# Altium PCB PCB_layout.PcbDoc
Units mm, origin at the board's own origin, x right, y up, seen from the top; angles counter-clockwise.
Board outline 62 x 48 mm, 2 copper layers (Top Layer, Bottom Layer); 48 components, 23 nets, 137 pads, 16 vias.
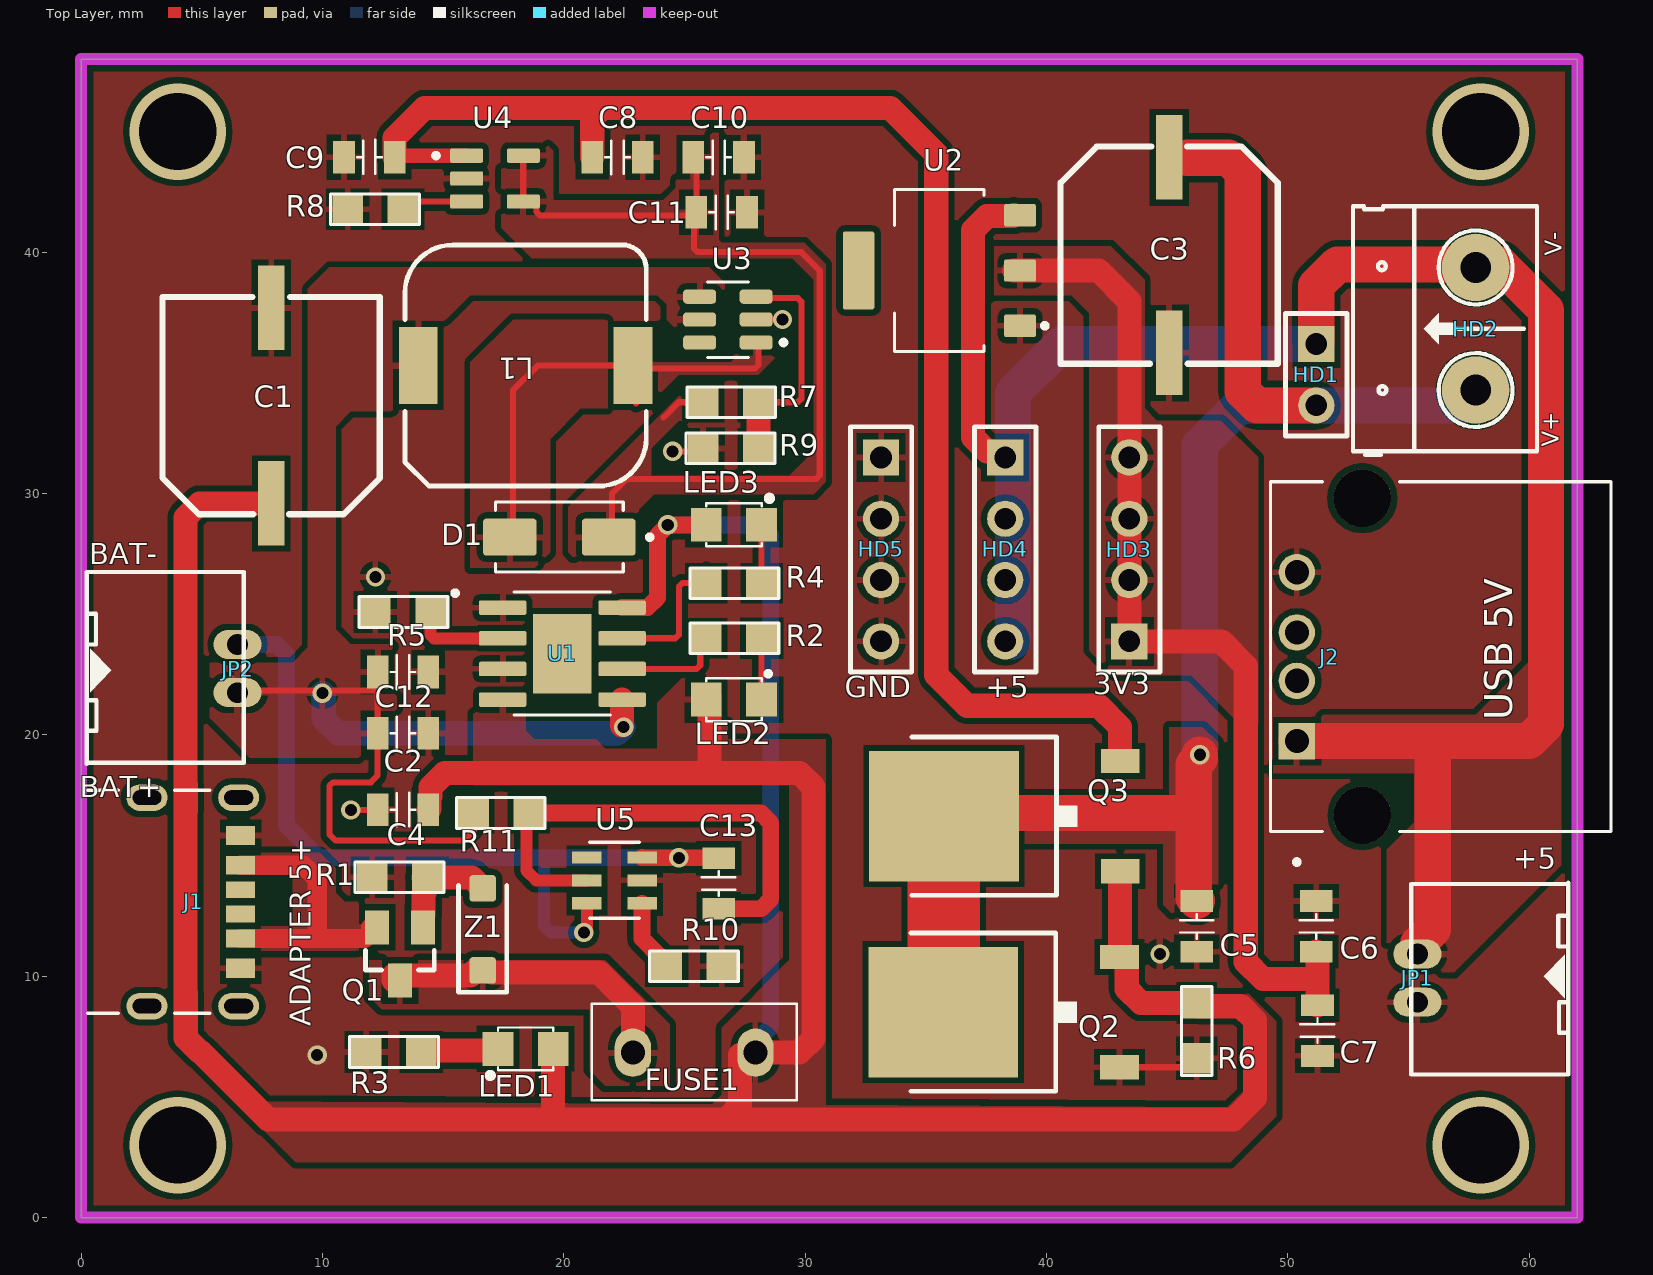
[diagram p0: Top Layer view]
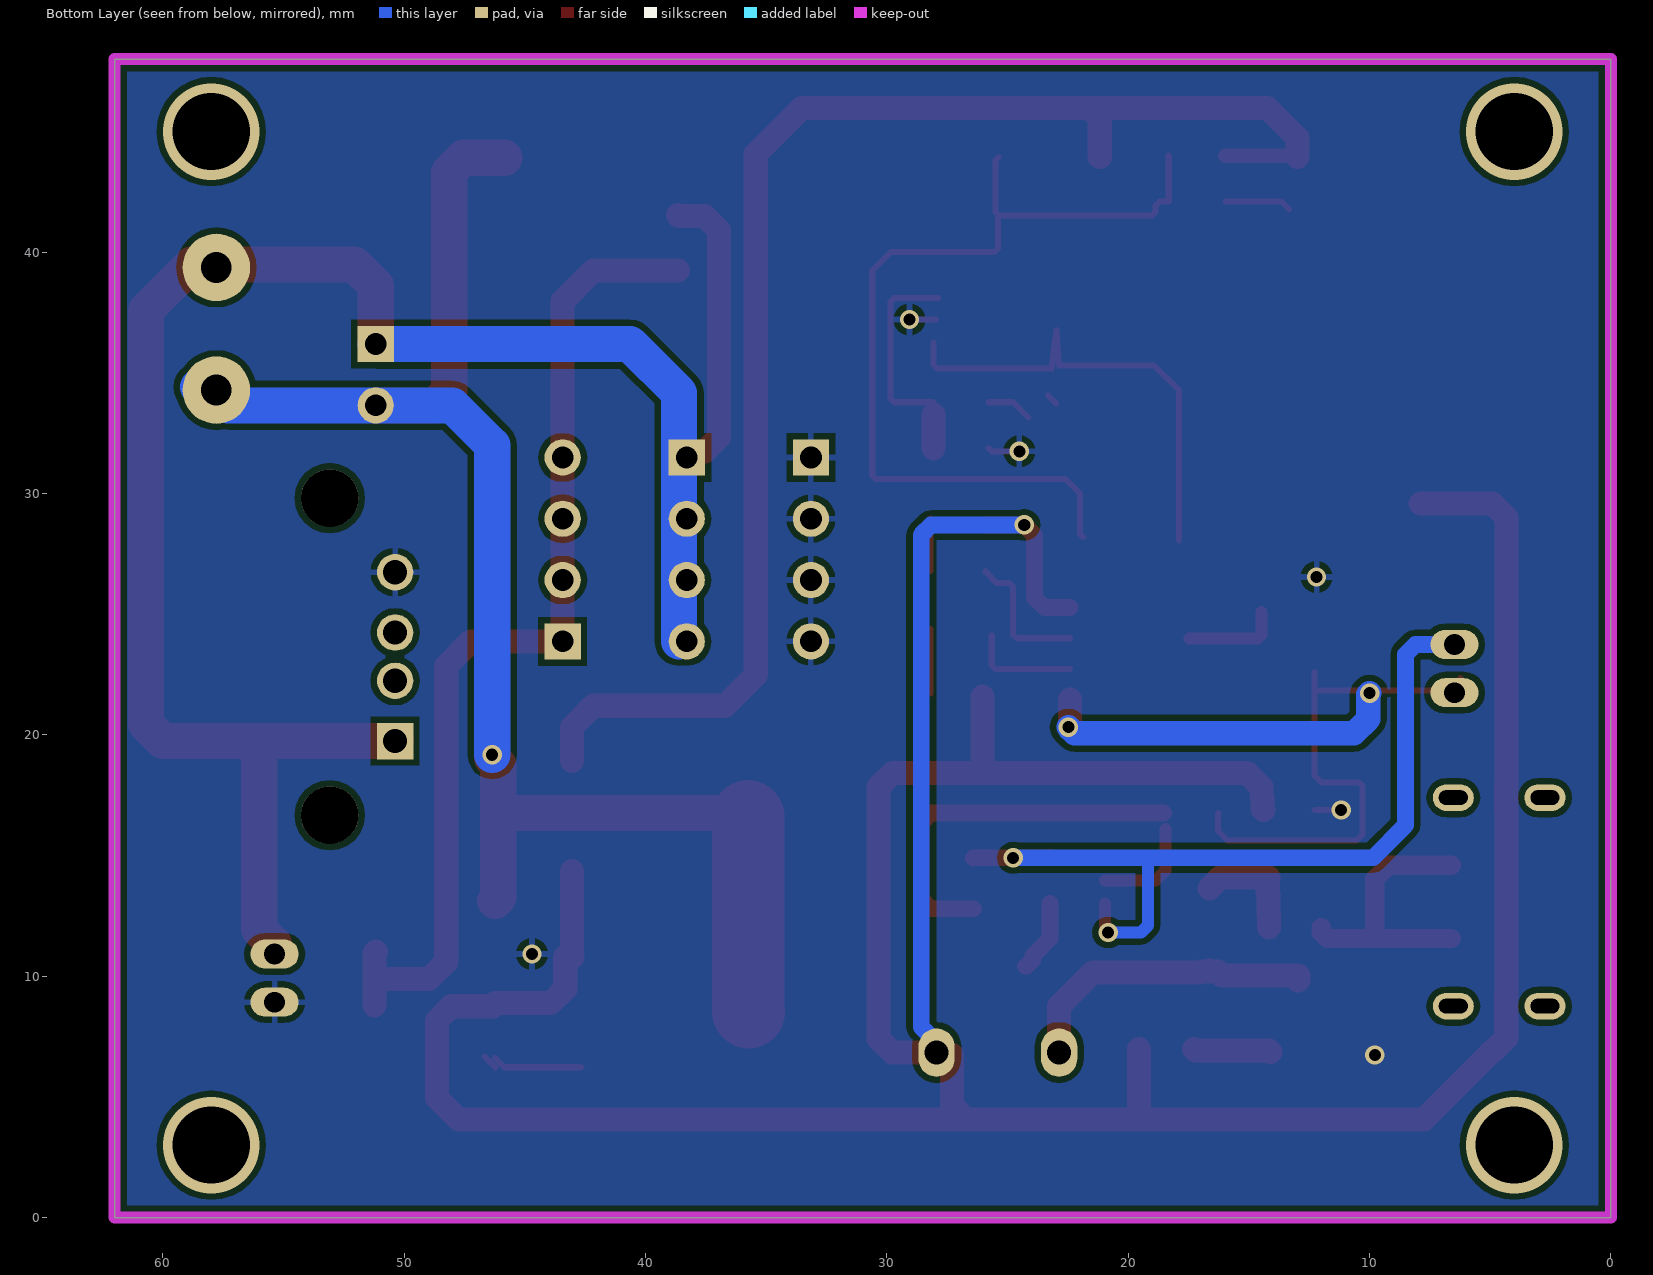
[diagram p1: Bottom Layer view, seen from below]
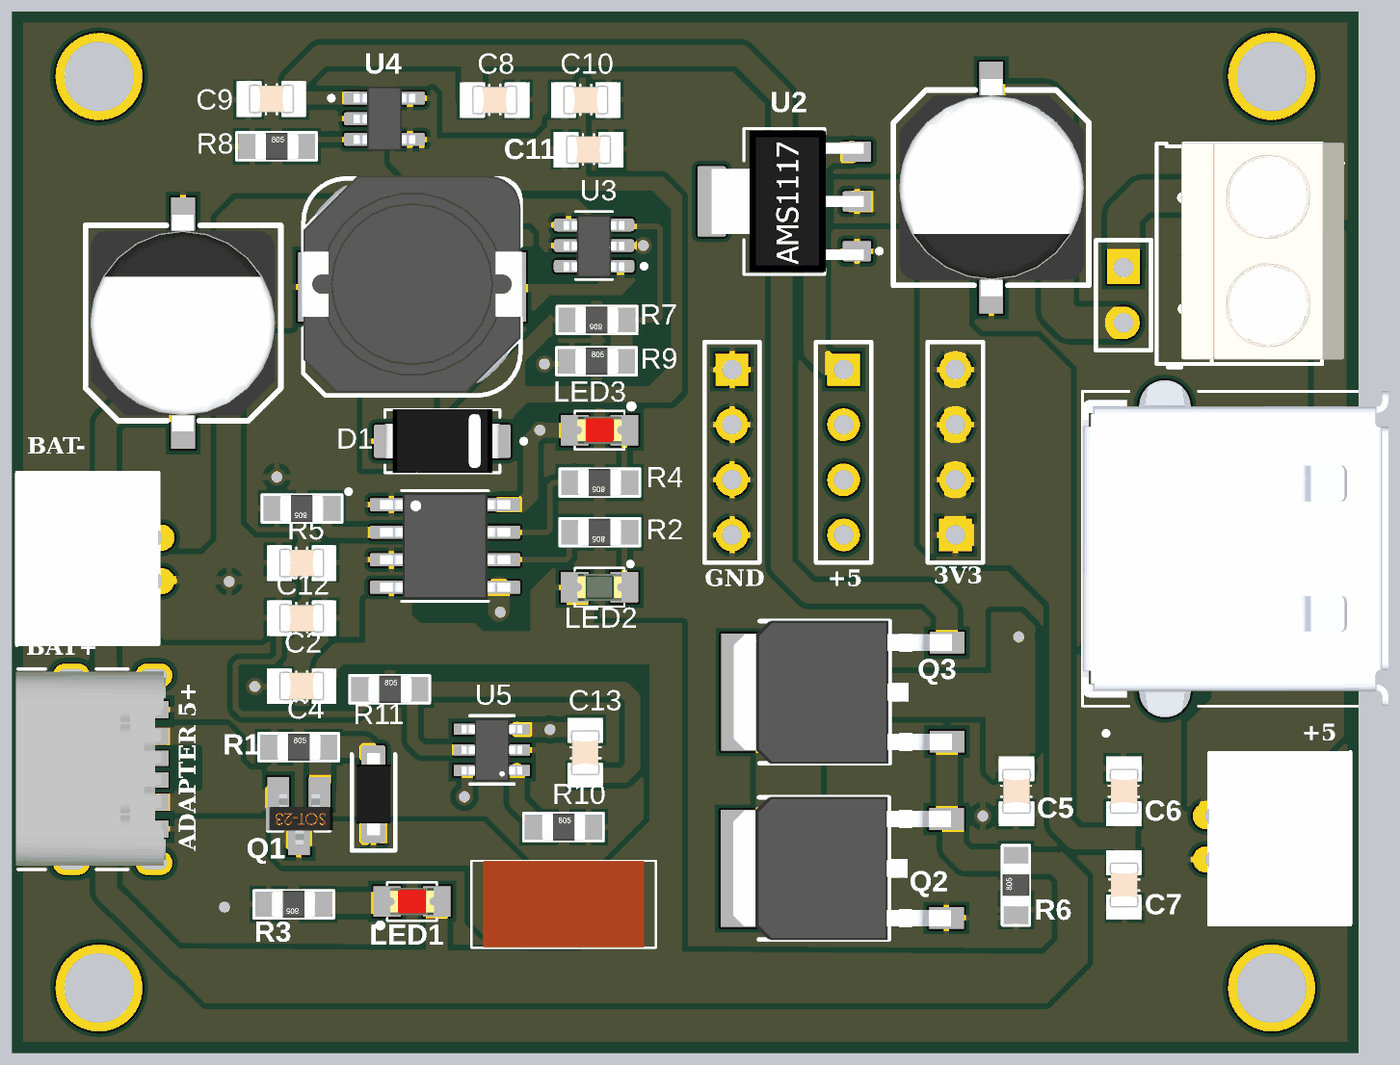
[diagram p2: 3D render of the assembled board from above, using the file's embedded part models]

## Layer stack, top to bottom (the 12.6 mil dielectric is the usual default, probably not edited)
Top Solder: solder mask 0.0102, Solder Resist, Dk 3.5
Top Layer: signal copper 0.0356
Dielectric 1: dielectric 0.32, FR-4, Dk 4.8
Bottom Layer: signal copper 0.0356
Bottom Solder: solder mask 0.0102, Solder Resist, Dk 3.5

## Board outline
0,0 0,48 62,48 62,0

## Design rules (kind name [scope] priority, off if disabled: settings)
Clearance [All] p1: gap=0.254 ignorepadtopadclearanceinfootprint=FALSE except(0: Arc-Hole Track-Hole SMDPad-Hole THPad-Hole Via-Hole Fill-Hole Poly-Hole Region-Hole Text-Hole)
HoleSize [All] p1: absolutevalues=TRUE maxlimit=1000 minlimit=0.5 maxpercent=80.000 minpercent=20.000
HoleToHoleClearance [All] p1 off: gap=0.254 allowstackedmicrovias=TRUE
MinimumSolderMaskSliver [All] p1 off: minsoldermaskwidth=0.254
PolygonConnect [All] p1: connectstyle=Relief reliefconductorwidth=0.254 reliefentries=4 polygonreliefangle="90 Angle" airgapwidth=0.254
RoutingVias [All] p1: holewidth=0.711 width=1.27 viastyle="Through Hole" minholewidth=0.5 minwidth=0.8 maxholewidth=1000 maxwidth=1000
SilkToSilkClearance [All] p1 off: silktosilkclearance=0.254
SilkToSolderMaskClearance [IsPad] p1 off: minsilkscreentomaskgap=0.254 clearancetoexposedcopper=TRUE
SolderMaskExpansion [All] p1: expansion=0.102 istentingtop=FALSE
Width [All] p1: maxlimit=1000 minlimit=0.254 preferedwidth=0.5
25 further rules are at their usual default settings.

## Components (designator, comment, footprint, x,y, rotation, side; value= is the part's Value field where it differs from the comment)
C1 "680uF" "Capacitor 680uF" 7.874,33.641 r90 top
C2 "22uF" "C 0805" 13.335,20.066 r180 top value=103
C3 "680uF" "Capacitor 680uF" 45.085,39.878 r270 top
C4 "22uF" "C 0805" 13.335,16.891 r0 top value=103
C5 "22uF" "C 0805" 46.228,12.065 r270 top value=103
C6 "100nF" "C 0805" 51.231,7.747 r90 top value=103
C7 "10uF" "C 0805" 51.181,12.065 r270 top value=103
C8 "100nF" "C 0805" 22.225,43.942 r180 top value=103
C9 "10uF" "C 0805" 11.938,43.942 r0 top value=103
C10 "1uF" "C 0805" 26.416,43.942 r180 top value=103
C11 "47uF" "C 0805" 26.543,41.656 r180 top value=103
C12 "22uF" "C 0805" 13.335,22.606 r180 top value=103
C13 "100nF" "C 0805" 26.416,13.843 r90 top value=103
D1 "Diode" DIODE_1N4007 19.812,28.194 r180 top value=1N5007
FUSE1 "FUSE_392" FUSE_392 25.4,6.858 r0 top
HD1 "Header_2" HDR1X2 51.181,36.195 r270 top value="Connector 2"
HD2 "Header 2" HED2 57.785,34.29 r90 top
HD3 "JP4" HDR1X4 43.434,23.876 r90 top value="Connector 4"
HD4 "JP4" HDR1X4 38.291,31.496 r270 top value="Connector 4"
HD5 "JP4" HDR1X4 33.147,31.496 r270 top value="Connector 4"
J1 "USB-C_6pin" MOLEX_2171750001 0.127,13.081 r270 top
J2 "USB-A1HSW6" OST_USB-A1HSW6 53.086,23.241 r90 top
JP1 "Domino_cong2_PH2.0" CON2_PH2.0_Cong 55.372,8.922 r90 top value="Connector 2"
JP2 "Domino_cong2_PH2.0" CON2_PH2.0_Cong 6.477,23.749 r270 top value="Connector 2"
L1 "22uH" CDRH104R 18.415,35.306 r90 top
LED1 "LED SMD" SM-LED-0805-Red 19.558,6.985 r180 top
LED2 "LED SMD" SM-LED-0805-Green 25.908,21.463 r0 top
LED3 "LED SMD" SM-LED-0805-Red 25.908,28.702 r0 top
Q1 "SI2301DS" MOSFET_P 13.208,10.922 r180 top
Q2 "AOD4185" TO252 38.227,8.509 r90 top
Q3 "AOD4185" TO252 38.253,16.631 r90 top
R1 "10K" SM-RES-0805 12.065,14.097 r0 top value=1K
R2 "1K" SM-RES-0805 28.194,24.003 r180 top
R3 "1K" SM-RES-0805 14.097,6.858 r180 top
R4 "1K" SM-RES-0805 28.194,26.289 r180 top
R5 "1.2K" SM-RES-0805 14.478,25.093 r180 top value=1K
R6 "10K" SM-RES-0805 46.228,6.604 r90 top value=1K
R7 "150K" SM-RES-0805 28.067,33.782 r180 top value=1K
R8 "12K" SM-RES-0805 11.049,41.783 r0 top value=1K
R9 "20K" SM-RES-0805 25.781,31.877 r0 top value=1K
R10 "100R" SM-RES-0805 24.257,10.414 r0 top value=1K
R11 "100R" SM-RES-0805 16.256,16.764 r0 top value=1K
U1 "TP4056" SOP127P600X175-9N 19.939,23.368 r0 top
U2 "AMS1117-3.3" SOT229P700X180-4N 35.56,39.243 r90 top
U3 "MT3608" SOT95P280X145-6N 26.797,37.211 r180 top
U4 "SY6280AAC" SOT95P285X130-5N 17.145,43.053 r0 top
U5 "DW06" TSOT-23_S6 22.098,13.97 r180 top
Z1 "Zener-Diode" SOD-123F 16.637,11.938 r90 top value=Z-Diode (schematic designator *1)

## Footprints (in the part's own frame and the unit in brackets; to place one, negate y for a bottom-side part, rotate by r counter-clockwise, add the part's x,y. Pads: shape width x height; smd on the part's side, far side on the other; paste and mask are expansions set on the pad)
"C 0805" [mm]
  rect 0.9x1.35 smd: 1(-1.05,0) 2(1.05,0)
  silkscreen extent -0.51,-0.69 0.51,0.71, body extent -1.6,-0.8 1.6,0.85, height 0.82
"Capacitor 680uF" [mm]
  rect 3.5x1.1 smd: 1(-4.05,0) 2(4.05,0)
  silkscreen extent -4.5,-4.5 4.5,4.5, body extent -5,-4.23 5,4.27, height 10.5
CDRH104R [mm]
  rect 3.2x1.6 smd: 1(0,4.45) 2(0,-4.45)
  silkscreen extent -5,-5 5,5, body extent -4.87,-5.1 5.13,5.1, height 4
CON2_PH2.0_Cong [mm] "CON2"
  oval 1.2x2 hole 0.864: 1(0,0) 2(2,0)
  silkscreen extent -3,-6.25 4.95,0.25, body extent -3.01,-6.35 4.94,0.25, height 5.2
DIODE_1N4007 [mm]
  rrect15% 2.21x1.53 smd: 1(2.05,0) 2(-2.05,0)
  silkscreen extent -3.85,-1.45 2.65,1.45, body extent -2.64,-1.47 2.64,1.45, height 2.41
FUSE_392 [mm]
  oval 1.5x2 hole 1: 1(-2.54,-0.025) 2(2.54,-0.025)
  silkscreen extent -4.25,-2 4.25,2, body extent -3.7,-2 3.7,2, height 8.3
HDR1X2 [mm] "Connector; Header; 2 Position"
  rect 1.5x1.5 hole 0.9: 1(0,0)
  round 1.5 hole 0.9: 2(2.54,0)
  silkscreen extent -1.27,-1.27 3.81,1.27, body extent -1.27,-1.27 3.81,1.27, height 7
HDR1X4 [mm] "Connector; Header; 4 Position"
  rect 1.5x1.5 hole 0.9: 1(0,0)
  round 1.5 hole 0.9: 2(2.54,0) 3(5.08,0) 4(7.62,0)
  silkscreen extent -1.27,-1.27 8.89,1.27, body extent -1.27,-1.27 8.89,1.27, height 7
HED2 [mil] "Header 2, 2 pin, hight 300mil, Pin to Pin 200, Colour Green"
  round 110 hole 50: 1(0,0) 2(200,0)
  silkscreen extent -106,-100 300,200, body extent -92,-140 302,155, height 394
MOLEX_2171750001 [mm]
  rect 0.7x1.2 smd mask+0.064: A5(-0.5,6.48) B5(0.5,6.48)
  rect 0.76x1.2 smd mask+0.064: A9(1.52,6.48) B9(-1.52,6.48)
  rect 0.8x1.2 smd mask+0.064: A12(2.75,6.48) B12(-2.75,6.48)
  oval 1.1x1.7 hole 0.6 slot 1.2 at 90 deg mask+0.064: SH1(-4.32,2.6) SH2(4.32,2.6) SH3(-4.32,6.4) SH4(4.32,6.4)
  silkscreen extent -4.62,0.15 4.62,5.2, body extent -4.5,0.05 4.44,6.95, height 3.28
MOSFET_P [mm]
  rect 1x1.4 smd: 1(-0.95,-1.1) 2(0.95,-1.1) 3(0,1.1)
  silkscreen extent -1.42,-0.15 1.42,0.66, body extent -1.57,-1.02 1.52,1.33, height 0.93
OST_USB-A1HSW6 [mm]
  rect 1.508x1.508 / inner round 1.508 / far side rect 1.508x1.508 hole 1: 1(-3.5,2.71)
  round 1.508 hole 1: 2(-1,2.71) 3(1,2.71) 4(3.5,2.71)
  round 2.38 hole 2.38 unplated: ""(-6.57,0) ""(6.57,0)
  silkscreen extent -8.61,-10.3 7.25,3.8, body extent -7.9,-10.3 7.9,3.8, height 7.6
SM-LED-0805-Green [mil]
  rect 50x55 smd: 1(0,0) 2(90,0)
  silkscreen extent 0,-35 104,45, body extent 5,-25 85,25, height 43
SM-LED-0805-Red [mil]
  rect 50x55 smd: 1(0,0) 2(90,0)
  silkscreen extent 0,-35 107,47, body extent 5,-25 85,25, height 43
SM-RES-0805 [mil]
  rect 50x47 smd: 1(0,0) 2(90,0)
  silkscreen extent -28,-25 117,25, body extent 6,-25 84,25, height 31
SOD-123F [mm] "SMD"
  rrect25% 1.1x1.1 smd: 1(-1.7,0) 2(1.7,0)
  silkscreen extent -2.6,-1 1.83,1, body extent -1.9,-0.8 1.9,0.8, height 1
SOP127P600X175-9N [mm]
  rrect25% 1.97x0.6 smd: 1(-2.475,1.905) 2(-2.475,0.635) 3(-2.475,-0.635) 4(-2.475,-1.905) 5(2.475,-1.905) 6(2.475,-0.635) 7(2.475,0.635) 8(2.475,1.905)
  rect 2.413x3.302 smd paste-3: 9(0,0)
  silkscreen extent -4.54,-2.55 2,2.6, body extent -3,-2.45 3,2.45, height 1.75
SOT95P280X145-6N [mm]
  rrect50% 1.37x0.59 smd: 1(-1.17,0.95) 2(-1.17,0) 3(-1.17,-0.95) 4(1.17,-0.95) 5(1.17,0) 6(1.17,0.95)
  silkscreen extent -2.4,-1.57 0.85,1.57, body extent -1.4,-1.42 1.4,1.48, height 1.45
SOT95P285X130-5N [mm]
  rrect25% 1.37x0.59 smd: 1(-1.175,0.95) 2(-1.175,0) 3(-1.175,-0.95) 4(1.175,-0.95) 5(1.175,0.95)
  silkscreen extent -2.54,0.85 -2.34,1.05, body extent -1.43,-1.48 1.43,1.48, height 1.4
SOT229P700X180-4N [mm]
  rrect15% 0.93x1.31 smd: 1(-2.29,-3.345) 2(0,-3.345) 3(2.29,-3.345)
  rrect15% 3.24x1.31 smd: 4(0,3.345)
  silkscreen extent -3.36,-4.47 3.36,1.86, body extent -3.25,-3.65 3.25,3.35, height 1.5
TO252 [mm]
  rect 1x1.6 smd: 1(-2.28,-4.8) 2(2.28,-4.8)
  rect 5.4x6.2 smd: 3(0,2.5)
  silkscreen extent -3.28,-3.02 3.28,3.84, body extent -3.3,-5.02 3.3,5.02, height 2.4
TSOT-23_S6 [mil]
  rect 48x20 smd paste+0 mask+4.02: 1(-45,37.4) 2(-45,0) 3(-45,-37.4) 4(45,-37.4) 5(45,0) 6(45,37.4)
  silkscreen extent -40,-62 40,62, body extent -55,-57 55,57, height 39

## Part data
C1 C3: library part Cap_680uF_SMD, "Cap SMD"
C2 C4 C5 C6 C7 C8 C9 C10 C11 C12 C13: library part "CAP SMD", "Cap SMD"
D1: library part Diode_1n4007, "Default Diode"
FUSE1: "Fuse Block 20A 500V 1 Circuit Blade Through Hole", Package=None
HD1: "Connector 2.54  2 PIN"
HD2: library part Header_green_2pin, "Header 2 (Green)"
HD3 HD4 HD5: library part Header_4, "Connector 2.54  4 PIN"
J1: "USB-C (USB TYPE-C) USB 2.0 Receptacle Connector 24 (6+18 Dummy) Position Surface Mount, Right Angle; Through Hole", Package=None
J2: Package=None
JP1 JP2: "Connector 2"
L1: library part INDUCTORS_CDRH104R, "POWER INDUCTORS (SMD Type)", Package=None
LED1 LED2 LED3: library part LED-SMD-0805
Q1: "N-Channel 50V 500mA _Ta_ 600mW _Ta_ Surface Mount SOT-23", Package="SC-59 NXP Semiconductors"
Q2 Q3: "P-Channel 40V 40A (Tc) 2.5W (Ta), 62.5W (Tc) Surface Mount TO-252, (D-Pak)", Package="TO-252 Alpha &amp; Omega Semiconductor"
R1 R2 R3 R4 R5 R6 R7 R8 R9 R10 R11: library part Resistor, "Resistor SMD"
U1: "Complete single cell Li-Ion battery with a constant current / constant voltage linear charger", Package=Package
U2: "Sot223/Pkg 1-Amp 3.3-Volt Low Drop Out Voltage Regulatator", Package=None
U3: "High Efficiency 1.2MHz2A Step Up Converter", Package=Package
U4: "USB Power Distribution SW Single 5.5V 1A 5-Pin SOT-23", Package="SOT-23-5 Silergy"
U5: "LT1784 - 2.5MHz, Over-The-Top Low Power, Rail-to-Rail Input and Output Op Amp in SOT-23", Package="SOT-23-6 Linear Technology"
Z1: "Zener Diode, TVS-unidirectional Diode", Supplier Part Number 1=637-BZT52B2V7

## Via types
v1: diameter 0.8, hole 0.5, Top Layer to Bottom Layer, tented both sides, 12 vias
v2: diameter 4, hole 3.2, Top Layer to Bottom Layer, 4 vias

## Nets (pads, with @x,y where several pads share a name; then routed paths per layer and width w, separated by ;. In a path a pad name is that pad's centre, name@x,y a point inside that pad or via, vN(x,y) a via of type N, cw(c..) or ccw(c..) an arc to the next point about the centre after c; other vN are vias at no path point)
3V3: C6.2 C7.2 HD3.1 HD3.2 HD3.3 HD3.4 U2.2 | length 42.4
  Top Layer w1: U2.2@38.651,39.243 42.164,39.243 43.434,37.973 HD3.4 HD3.3 HD3.2 HD3.1 47.244,23.876 48.26,22.86 48.26,10.595 48.974,9.881 51.231,9.881 ; C7.2 51.231,10.965 51.231,9.881 ; C6.2 51.231,9.881
+5V: C3.1 C5.1 HD1.2 HD2.1 Q2.3 Q3.3 | length 65.7
  Top Layer w1.5: Q3.3 35.886,16.764 36.763,16.764 46.101,16.764 ; 45.847,43.914 47.547,43.914 48.133,43.328 48.133,34.241 48.719,33.655 HD1.2 ; C5.1 46.101,13.242 46.101,16.764 ; v1(46.355,19.177) 46.355,19.029 46.101,18.775 46.101,16.764
  Top Layer w3: Q2.3 35.74,8.522 35.74,16.618 Q3.3
  Bottom Layer w1.5: v1(46.355,19.177) 46.355,32.004 48.006,33.655 51.943,33.655 57.3,33.655 58.062,34.417 HD2.1@58.547,34.417
ADAPTER: C1.1 C4.2 FUSE1.2 LED1.1 LED2.1 LED3.1 Q2.2 Q3.1 R6.2 U1.4 U1.8 | length 158.4
  Top Layer w0.7: U1.8 23.466,25.273 23.876,25.683 23.876,28.271 v1(24.307,28.702) LED3.1
  Top Layer w1: C1.1 4.904,29.591 4.318,29.005 4.318,17.954 4.331,17.941 4.331,16.861 4.318,16.848 4.318,9.314 4.331,9.301 4.331,7.444 4.917,6.858 4.953,6.858 7.747,4.064 19.558,4.064 ; C4.2 14.435,16.941 14.435,17.43 14.478,17.473 14.478,17.829 15.064,18.415 17.464,18.415 26.035,18.415 ; LED1.1 19.558,4.064 ; LED2.1@26.035,21.59 26.035,18.415 ; FUSE1.2@27.94,6.731 27.305,6.731 27.305,4.65 26.719,4.064 ; FUSE1.2 29.767,6.833 30.353,7.418 30.353,17.829 29.767,18.415 26.035,18.415 ; Q2.2 Q2.2@43.053,10.789 ; Q3.1 Q2.2@43.053,10.789 ; 19.558,4.064 26.719,4.064 ; 26.719,4.064 47.752,4.064 48.641,4.953 48.641,8.169 48.055,8.755 46.325,8.755 46.228,8.852 R6.2 43.913,8.89 43.327,9.476 43.327,10.789 Q2.2@43.053,10.789
  Bottom Layer w0.7: v1(24.307,28.702) 28.165,28.702 28.575,28.292 28.575,7.893 27.94,7.258 FUSE1.2
BAT+: C2.2 C12.2 JP2.2 L1.1 R11.1 U1.5 U3.4 U3.5 | length 37
  Top Layer w0.254: 6.223,22.352 6.731,21.844 v1@9.894,21.844 ; v1(9.994,21.729) 9.994,21.744 v1@9.894,21.844 ; C12.2 12.285,21.717 ; R11.1 16.278,16.742 16.278,16.024 15.875,15.621 10.541,15.621 10.287,15.875 10.287,17.885 10.436,18.034 11.997,18.034 12.285,18.322 C2.2 12.285,21.717 ; v1@22.414,20.385 v1(22.479,20.32) ; v1@9.894,21.844 12.158,21.844 12.285,21.717
  Top Layer w1: v1@22.414,20.385 U1.5
  Bottom Layer w1: v1(9.994,21.729) 10.052,21.671 10.052,20.652 10.638,20.066 22.225,20.066 v1(22.479,20.32)
BAT-: C13.2 JP2.1 U5.3 U5.6 | length 35.1
  Top Layer w0.5: v1(20.828,11.811) 20.955,11.938 U5.6
  Top Layer w0.7: U5.3 23.255,14.907 v1(24.765,14.907) 26.402,14.907 C13.2
  Bottom Layer w0.5: 19.177,14.907 19.177,12.104 19.47,11.811 v1(20.828,11.811)
  Bottom Layer w0.7: JP2.1 8.099,23.749 8.509,23.339 8.509,16.256 9.858,14.907 19.177,14.907 v1(24.765,14.907)
BOOT_5V: C8.2 C9.2 Q3.2 U4.1 | length 60.8
  Top Layer w0.6: C9.2@13.43,44.003 U4.1
  Top Layer w1: C9.2 12.988,44.738 14.224,45.974 21.175,45.974 21.463,45.974 21.526,45.91 ; C8.2 21.175,45.119 21.175,45.559 21.59,45.974 33.528,45.974 35.433,44.069 35.433,22.479 36.703,21.209 42.164,21.209 43.048,20.325 43.048,18.911 Q3.2
GND: C1.2 C2.1 C3.2 C4.1 C5.2 C6.1 C7.1 C8.1 C9.1 C10.1 C11.1 C12.1 HD5.1 HD5.2 HD5.3 HD5.4 J1.A12 J1.B12 J2.4 JP1.1 Q2.1 R1.1 R3.2 R5.2 R6.1 R8.1 R9.1 R10.2 U1.1 U1.3 U2.1 U3.2 U4.2 U5.2 | length 7.9
  Top Layer w0.254: v1(11.176,16.891) C4.1 ; v1(24.511,31.75) 25.654,31.75 R9.1 ; U3.2 v1(29.064,37.211) ; Q2.1@42.663,6.229 45.853,6.229 R6.1 ; R6.1@46.228,6.229 R6.1@46.67,6.671
  other v1: 9.779,6.731 44.704,10.922 12.192,26.543
INPUT: J1.A9 J1.B9 Q1.2 | length 11.6
  Top Layer w0.8: J1.A9 9.779,11.561 ; J1.B9 9.193,14.601 9.779,14.015 9.779,11.561 ; Q1.2@12.004,12.022 12.004,11.822 11.743,11.561 9.779,11.561
Net*1_1: FUSE1.1 Q1.3 Z1.1 | length 12.7
  Top Layer w1: Q1.3@12.954,9.822 12.954,10.022 13.529,10.022 13.54,10.033 16.12,10.033 16.275,10.188 16.587,10.188 Z1.1 16.687,10.188 16.999,10.188 17.027,10.16 21.463,10.16 22.86,8.763 FUSE1.1
Net*1_2: Q1.1 R1.2 Z1.2 | length 4.7
  Top Layer w1: Q1.1 14.158,12.515 14.186,12.543 14.186,13.414 14.216,13.444 R1.2@14.216,14.097 ; R1.2@14.186,14.097 16.178,14.097 Z1.2
NetC10_2: C10.2 C11.2 D1.2 R7.2 U4.4 U4.5 | length 40
  Top Layer w0.254: U4.5 U4.4 18.694,42.103 18.862,41.935 18.862,41.678 19.011,41.529 C11.2@25.366,41.529 ; D1.2 21.989,28.321 21.989,29.99 22.606,30.607 24.13,30.607 24.257,30.607 30.458,30.607 30.607,30.756 30.607,39.243 29.845,40.005 25.549,40.005 25.4,40.154 25.4,41.495 C11.2@25.366,41.529 ; 24.13,33.147 24.765,33.782 R7.2 ; C10.2 25.493,43.815 C11.2 C11.2@25.366,41.529
NetC13_1: C13.1 R11.2 U5.5 | length 20.1
  Top Layer w0.5: 18.446,16.098 18.446,14.38 18.856,13.97 U5.5
  Top Layer w0.7: R11.2 28.165,16.764 28.575,16.354 28.575,13.203 28.165,12.793 C13.1
NetD1_1: D1.1 L1.2 U3.1 | length 21
  Top Layer w0.254: D1.1@17.889,28.067 17.889,34.272 18.923,35.306 L1.2 22.962,36.779 23.167,35.179 27.918,35.179 28.067,35.328 U3.1@28.067,36.261 ; L1.2@22.992,33.744 L1.2@23.31,34.061
NetLED1_2: LED1.2 R3.1 | length 3.2
  Top Layer w1: R3.1 14.16,6.921 17.209,6.921 LED1.2
NetLED2_2: LED2.2 R2.1 | length 2.7
  Top Layer w0.254: LED2.2@28.194,21.717 R2.1@28.194,24.384
NetLED3_2: LED3.2 R4.1 | length 2.2
  Top Layer w0.254: R4.1@28.194,26.797 LED3.2@28.194,28.956
NetR2_2: R2.2 U1.6 | length 4.5
  Top Layer w0.254: U1.6 25.505,22.733 25.654,22.882 R2.2@25.654,24.13
NetR4_2: R4.2 U1.7 | length 5.8
  Top Layer w0.254: U1.7 24.616,24.003 24.765,24.152 24.765,26.14 24.914,26.289 25.438,26.289 25.908,26.759 R4.2@25.908,26.797
NetR5_1: R5.1 U1.2 | length 4
  Top Layer w0.5: R5.1 14.478,24.152 14.627,24.003 U1.2
NetR7_1: R7.1 R9.2 U3.3 | length 9.3
  Top Layer w0.254: U3.3@27.875,38.1 29.696,38.1 29.845,37.951 29.845,33.931 29.696,33.782 R7.1
  Top Layer w1: R9.2 R7.1@28.067,33.274
NetR8_2: R8.2 U4.3 | length 2.8
  Top Layer w0.254: R8.2 13.655,42.103 U4.3
NetR10_1: R10.1 U5.1 | length 3
  Top Layer w0.7: U5.1 23.241,11.557 23.972,10.826 23.972,10.661 24.219,10.414 R10.1
V_OUT: HD1.1 HD2.2 HD4.1 HD4.2 HD4.3 HD4.4 J2.1 JP1.2 U2.3 | length 85.4
  Top Layer w1: HD4.1@38.358,31.746 37.543,31.746 36.957,32.332 36.957,40.912 37.543,41.498 38.616,41.498 U2.3@38.651,41.533
  Top Layer w1.5: J2.1 56.007,19.741 ; HD1.1 51.181,38.618 52.06,39.497 58.547,39.497 58.801,39.497 60.698,37.6 60.698,20.446 59.993,19.741 56.007,19.741 ; JP1.2@55.409,11.341 56.007,11.939 56.007,19.741
  Bottom Layer w1.5: HD4.4@38.608,23.876 38.608,31.496 38.608,34.163 40.64,36.195 HD1.1
pads on no net: J1.A5 J1.B5 J1.SH1 J1.SH2 J1.SH3 J1.SH4 J2. J2.2 J2.3 U1.9 U2.4 U3.6 U5.4
copper on no net:
  other v2: 4,3 58,3 4,45 58,45

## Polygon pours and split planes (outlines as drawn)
GND on Top Layer "GND_L01_P010" (solid, remove dead copper, pour order 10): 0,0 0,48 62,48 62,0
3V3 on Top Layer "NONET_L-01_P-001" (solid, remove dead copper, pour order 17): 44.577,33.02 47.244,33.02 48.768,31.496 48.768,20.447 48.006,20.447 44.577,23.876
3V3 on Top Layer "NONET_L-01_P-001" (solid, remove dead copper, pour order 16): 47.752,20.701 45.974,22.479 42.799,22.479 41.783,23.495 41.783,37.465 41.021,38.227 37.846,38.227 37.846,40.259 42.672,40.259 44.069,38.862 44.069,33.528 44.577,33.02
V_OUT on Top Layer "NONET_L-01_P-001" (solid, remove dead copper, pour order 14): 49.403,20.828 57.785,20.828 60.071,23.114 61.341,21.844 61.341,14.605 56.896,10.16 54.102,10.16 54.102,15.24 55.245,16.383 55.245,18.415 49.403,18.415
Net*1_1 on Top Layer "NONET_L-01_P-001" (solid, remove dead copper, pour order 13): 21.717,10.668 24.384,8.001 24.384,5.461 21.717,5.461 21.082,6.096 21.082,8.636 12.446,8.636 11.938,9.144 11.938,10.668
ADAPTER on Top Layer "NONET_L-01_P-001" (solid, remove dead copper, pour order 12): 6.349,4.827 8.89,2.286 47.625,2.286 49.53,4.191 49.53,8.128 48.387,9.271 48.26,9.271 48.26,5.334 47.498,4.572
BAT+ on Top Layer "NONET_L-01_P-001" (solid, remove dead copper, pour order 9): 5.334,20.701 6.985,19.05 13.081,19.05 13.081,23.495 12.827,23.749 11.176,23.749 10.541,24.384 10.541,32.766 11.176,33.401 14.986,33.401 14.986,37.084 16.129,38.227 23.876,38.227 24.257,37.846 24.257,37.211 24.638,36.83 26.416,36.83 26.67,37.084 26.67,38.735 26.035,39.37 10.287,39.37 9.398,38.481 9.398,23.622 8.763,22.987 5.334,22.987
NetD1_1 on Top Layer "NONET_L-01_P-001" (solid, remove dead copper, pour order 4): 16.129,26.924 18.796,26.924 19.431,27.559 19.431,32.258 20.701,33.528 23.749,33.528 23.749,33.909 24.765,34.925 28.067,34.925 28.829,35.687 28.829,36.703 27.305,36.703 27.051,36.449 27.051,35.56 26.924,35.433 23.876,35.433 23.876,37.211 17.907,37.211 16.129,35.433
NetC10_2 on Top Layer "NONET_L-01_P-001" (solid, remove dead copper, pour order 7): 17.399,44.577 19.177,44.577 19.558,44.196 19.558,42.164 24.13,42.164 24.638,42.672 24.638,44.704 24.892,44.958 26.416,44.958 26.416,40.513 26.543,40.386 29.972,40.386 30.861,39.497 30.861,30.48 30.353,29.972 23.749,29.972 23.114,29.337 23.114,27.178 20.574,27.178 20.193,27.559 20.193,29.464 23.241,32.512 25.273,34.544 26.67,34.544 26.67,33.02 24.765,33.02 23.622,31.877 23.622,30.734 29.337,30.734 30.353,31.75 30.353,38.862 29.464,39.751 18.669,39.751 17.399,41.021
INPUT on Top Layer "NONET_L-01_P-001" (solid, remove dead copper, pour order 5): 12.827,13.081 12.827,11.303 12.573,11.049 5.969,11.049 5.715,11.303 5.715,12.065 8.636,12.065 8.763,12.192 8.763,14.097 8.636,14.224 5.715,14.224 5.715,14.986 5.842,15.113 9.906,15.113 10.541,14.478 10.541,13.462 10.922,13.081
+5V on Top Layer "NONET_L-01_P-001" (solid, remove dead copper, pour order 3): 37.338,15.494 44.831,15.494 44.831,12.954 45.466,12.319 47.117,12.319 47.117,19.685 46.482,20.32 45.085,20.32 45.085,16.891 37.084,16.891
ADAPTER on Top Layer "NONET_L-01_P-001" (solid, remove dead copper, pour order 1): 16.256,21.844 18.288,21.844 18.415,21.717 18.415,20.193 18.796,19.812 21.336,19.812 21.717,19.431 23.876,19.431 23.876,21.336 24.892,22.352 26.797,22.352 26.797,19.812 30.861,19.812 30.861,4.064 30.734,3.937 25.908,3.937 25.908,4.445 26.543,5.08 26.543,7.874 29.337,10.668 29.337,17.907 16.256,17.907 16.256,19.812
GND on Bottom Layer "GND_L02_P011" (solid, remove dead copper, pour order 11): 0,0 0,48 62,48 62,0

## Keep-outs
Keep-Out Layer:
  the board outline again, w0.5

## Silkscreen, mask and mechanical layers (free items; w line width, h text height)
Top Overlay:
  text "V-" at 61.605,39.846 h1.2 r90
  text "V+" at 61.478,31.935 h1.2 r90
  text "BAT-" at 0.323,26.779 h1.5
  text "3V3" at 41.934,21.388 h1.5
  text "+5" at 37.491,21.277 h1.5
  text "GND" at 31.647,21.261 h1.5
  text "USB 5V" at 59.692,20.603 h2 r90
  text "BAT+" at -0.055,17.133 h1.5
  text "+5" at 59.335,14.165 h1.5
  text "ADAPTER 5+" at 9.812,7.922 h1.5 r90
